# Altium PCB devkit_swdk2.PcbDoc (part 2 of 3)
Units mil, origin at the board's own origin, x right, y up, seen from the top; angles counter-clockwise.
Board outline 2700 x 2100 mil, 4 copper layers (Component Side, Internal Plane 1, Internal Layer 2, Bottom Layer), stack 57.8 mil thick; 223 components, 143 nets, 656 pads, 485 vias.
Unrouted connection lines stored in the file: 72.
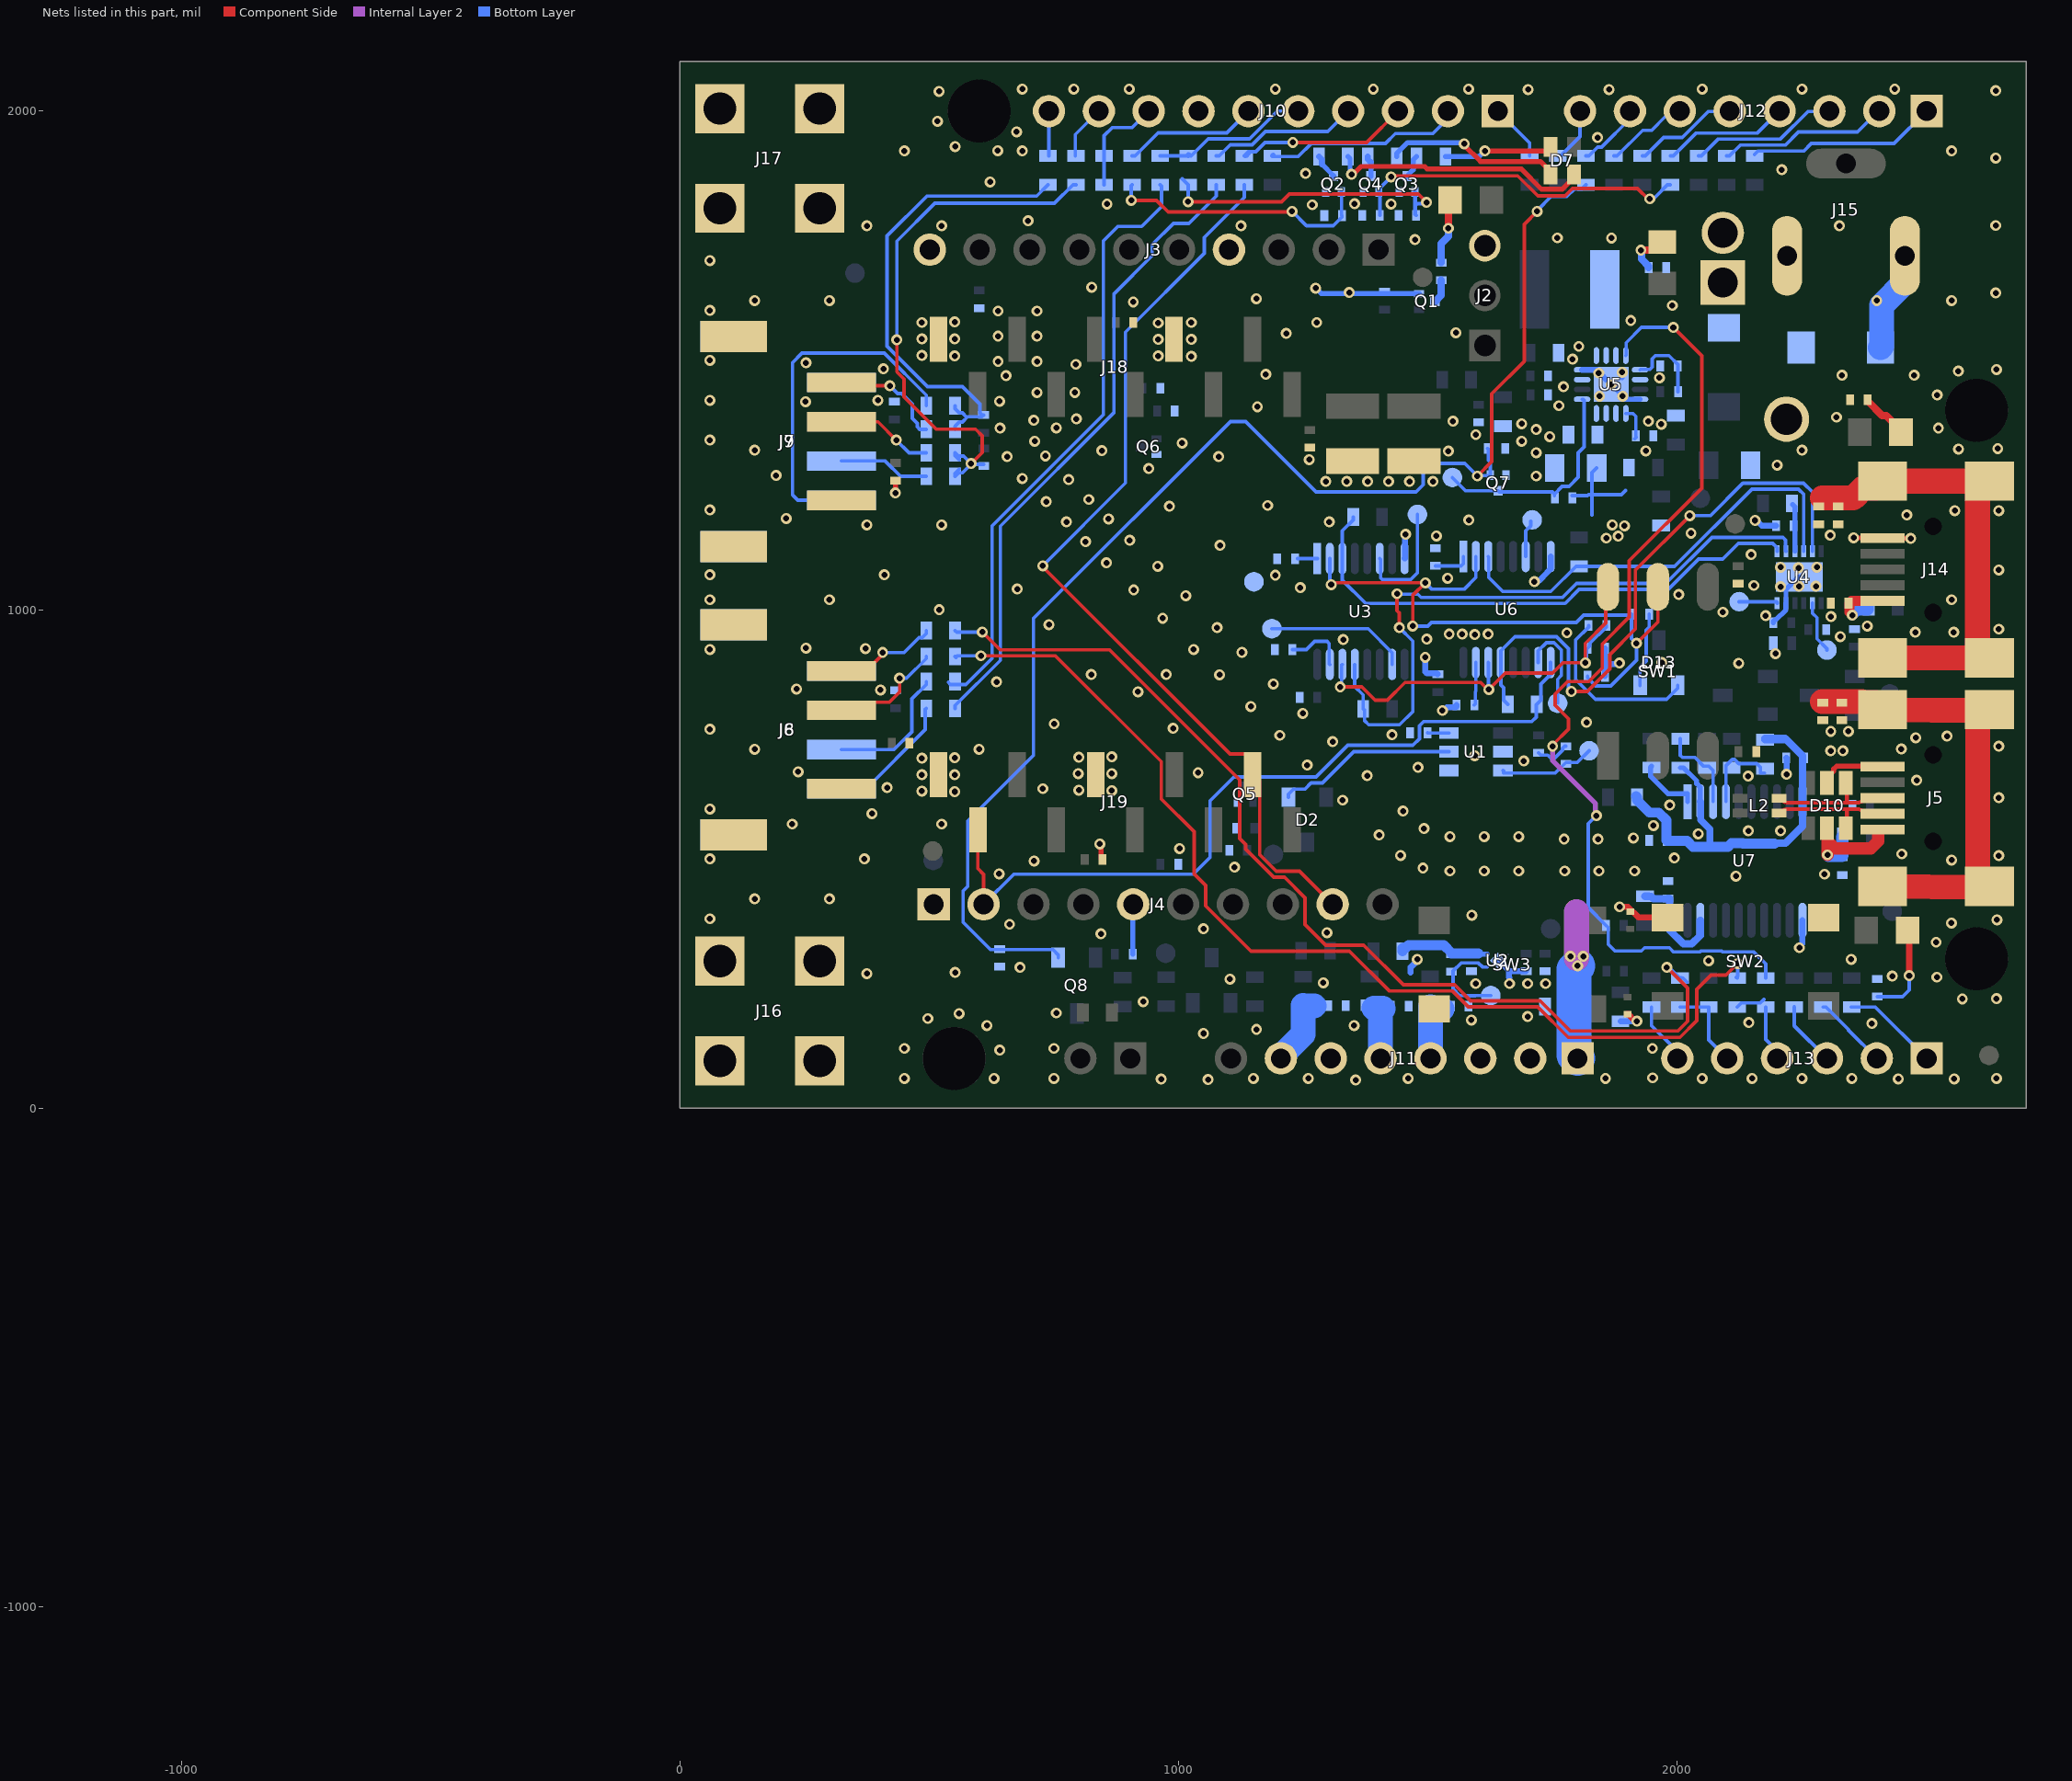
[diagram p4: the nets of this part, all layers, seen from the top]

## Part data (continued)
R8 R9 R10 R14 R15 R16 R17 R24 R25 R35: library part 1000796, "Resistor, 100K, 1%, 1/16W, 0402", Manufacturer1="Bourns Inc", Manufacturer2="Samsung Electro-Mechanics America, Inc", Manufacturer_Part_Number1=CR0402-FX-1003GLF, Manufacturer_Part_Number2=RC1005F104CS, Operating_Temperature="-55°C ~ 155°C", Power="0.063W, 1/16W", Resistance_Ohms=100k, Resistor_Package="0402 (1005 Metric)", Temperature_Coefficient=±100ppm/°C, Tolerance=±1%
R11 R12 R19 R20 R21 R22 R26 R32 R56: library part 1000795, "Resistor, 10K, 1%, 1/16W, 0402", Manufacturer1="Bourns Inc", Manufacturer_Part_Number1=CR0402-FX-1002GLF, Manufacturer_Part_Number2=CR0402-FX-1002GAS, Operating_Temperature="-55°C ~ 155°C", Power="0.063W, 1/16W", Resistance_Ohms=10k, Resistor_Package="0402 (1005 Metric)", Temperature_Coefficient=±100ppm/°C, Tolerance=±1%
R18 R23: library part 1000797, "Resistor, 1M, 1%, 1/16W, 0402", Manufacturer1="Bourns Inc", Manufacturer2="Samsung Electro-Mechanics America, Inc", Manufacturer_Part_Number1=CR0402-FX-1004GLF, Manufacturer_Part_Number2=RC1005F105CS, Operating_Temperature="-55°C ~ 155°C", Power="0.063W, 1/16W", Resistance_Ohms=1M, Resistor_Package="0402 (1005 Metric)", Temperature_Coefficient=±100ppm/°C, Tolerance=±1%
R30 R31: library part 1001865, "Resistor, 0, 1/16W, 0402", Manufacturer1="Bourns Inc", Manufacturer2="Samsung Electro-Mechanics America, Inc", Manufacturer_Part_Number1=CR0402-J/-000GLF, Manufacturer_Part_Number2=RCS1005J000CS, Operating_Temperature="-55C ~ 155C", Power=1/16W, Resistance_Ohms=0, Resistor_Package="0402 (1005 Metric)"
R33: library part 1001436, Manufacturer1="Panasonic Electronic Components", Manufacturer_Part_Number1=ERJ-2RKF7153X, Power=1/10W, Resistance_Ohms=715K, Resistor_Package="0402 (1005 Metric)", Tolerance=1%
R36: library part 1001435, Manufacturer1="Panasonic Electronic Components", Manufacturer_Part_Number1=ERJ-2RKF1783X, Power=1/10W, Resistance_Ohms=178K, Resistor_Package="0402 (1005 Metric)", Tolerance=1%
R54 R55: library part 1000583, "Resistor, 2.2K, 1%, 1/10W, 0402", Manufacturer1="Panasonic Electronic Components", Manufacturer_Part_Number1=ERJ-2RKF2201X, Operating_Temperature="-55°C ~ 155°C", Power="0.1W, 1/10W", Resistance_Ohms=2.2k, Resistor_Package="0402 (1005 Metric)", Temperature_Coefficient=±100ppm/°C, Tolerance=±1%
SB1 SB2 SB3 SB4 SB5 SB6 SB7 SB8 SB9 SB10 SB11 SB12 SB13 SB14 SB15 SB16 SB17 SB18 SB19 SB20 SB21 SB22 SB23 SB24 SB25 SB26 SB27 SB28 SB29 SB30 SB34 SB35 SB36 SB37 SB38 SB39 SB40 SB41 SB42 SB43 SB44 SB45 SB46 SB47 SB53: library part 1002269, "Resistor, Solder Bridge, 0, 1/10W, 0603", Manufacturer1="Panasonic Electronic Components", Manufacturer2=Yageo, Manufacturer_Part_Number1=ERJ-3GEY0R00V, Manufacturer_Part_Number2=RC0603JR-070RL, Operating_Temperature="-55°C ~ 155°C", Power=1/10W, Resistance_Ohms=0, Resistor_Package="0603 (1608 Metric)"
SB31 SB32 SB33 SB48 SB49 SB50 SB51 SB52: library part "Solder Bridge, Open"
SW1: library part 1002262, "Switch, SPST, DIP 3, 20V, 0.1A, Washable, Raised Actuator, SMD", Contact_Current_Rating_at_Voltage=0.1A, Manufacturer1=CTS, Manufacturer_Part_Number1=219-3MSTR, Operating_Temperature="-55°C ~ 85°C"
SW2 SW3: library part 1001120, "Switch, SPST-NO, 12V, 0.05A, 6.00x6.00mm, SMD", Contact_Current_Rating_at_Voltage="0.05A @ 12VDC", Current_Rating=-, Manufacturer1="C&K Components", Operating_Force=160gf, Operating_Temperature="-20°C ~ 60°C"
TP1 TP2 TP3 TP5 TP7 TP8 TP9 TP11 TP12 TP13 TP14 TP16 TP17 TP18 TP19 TP20: library part TP_1mm, "TEST POINT, SMD 1mm"
TP15: library part 1002259, "Connector, PC Test Point, 1 pin, Black, Silver Plate, TH, 3.17mmx11.30mm", Color=Black, Manufacturer1="Keystone Electronics", Manufacturer_Part_Number1=5011
U1: library part 1002129, "IC, Timer, 0.1-7200s, 1%, 1.8V-5.5V, TSOT-23-6", Manufacturer1="Texas Instruments", Manufacturer_Part_Number1=TPL5111DDCR, Operating_Temperature="-40C to +105C", Package_Case=TSOT-23-6, Voltage_Supply_Max=5.5V, Voltage_Supply_Min=1.8V, Voltage_Supply_Typical=3.3V
U2: library part 1001908, "IC, LDO, 1.8V, 300mA, 4-UDFN, 1.0x1.0mm", Current_Supply=300mA, Manufacturer1="ON Semiconductor", Operating_Temperature="-40C to 85C", Package_Case=4-UDFN, Voltage_Supply_Max="5.5 V", Voltage_Supply_Min=1.7V
U3 U6: library part 1001013, "IC, Multiplexer, Dual, 4:1, 4.5V-5.5V, SSOP-16", Manufacturer1="Texas Instruments", Package_Case=SSOP-16, Voltage_Supply_Typical=-
U4: library part 1001128, "IC, Interface, UART-USB, 5V, DFN, 3x3mm", Current_Supply=8mA, Manufacturer1="FTDI, Future Technology Devices International Ltd", Manufacturer_Part_Number1=FT234XD-R, Operating_Temperature="-40°C ~ 85°C", Package_Case="12-VFDFN Exposed Pad", Voltage_Supply_Max=5.5V, Voltage_Supply_Min=2.97V, Voltage_Supply_Typical=-
U5: "IC, Buck, ADJ, 3V-17V , 2A, QFN", Manufacturer1="Texas Instruments", Manufacturer_Part_Number1=TPS62140RGTR, Operating_Temperature="-40°C ~ 85°C", Package_Case="16-VFQFN Exposed Pad", Voltage_Supply_Typical=-
U7: library part 1001048, "IC, Level Shifter, Bidirectional, OD/Push/Pull , TSSOP-20", Manufacturer1="Texas Instruments", Operating_Temperature="-40°C ~ 85°C", Package_Case="20-TSSOP (0.173\", 4.40mm Width)", Voltage_Supply_Typical=-

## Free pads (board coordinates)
  round 125.98 hole 125.98: 0(550,100) 0(600,2000) 0(2600,300) 0(2600,1400)
  round 200 on Mech1: 0(550,100) 0(600,2000) 0(2600,300) 0(2600,1400)
  rect 39.37x39.37 on Mech13: 0(1800,100) 1(1640,2000) 1(2000,100) 1(2500,2000) 2(1640,2000) 2(2000,100) 2(2500,2000)
  oval 20x50 on Mech15: 3(1069.83,1431.81) 4(361.34,668.98) 5(280,295) 6(280,2005) 7(2600,1400) 8(600,2000) 9(550,100) 11(2220,1709.69)
  oval 50x20 on Mech15: 10(2529.69,313.39) 12(1800,100) 13(2000,100) 14(2500,2000) 15(1640,2000) 16(190.32,1122.61)

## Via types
v1: diameter 22, hole 12, Component Side to Bottom Layer, 485 vias

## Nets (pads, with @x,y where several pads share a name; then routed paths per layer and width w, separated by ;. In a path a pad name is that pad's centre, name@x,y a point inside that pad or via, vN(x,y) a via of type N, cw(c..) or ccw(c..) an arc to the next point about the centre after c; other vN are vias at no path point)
ARD_A0: J13.6 SB24.2 | length 124.4
  Bottom Layer w7: SB24.2@1948.25,203 1948.25,165.75 2000,114 J13.6@2000,100
ARD_A1: J13.5 SB25.2 SB53.2 | length 175.7
  Bottom Layer w7: SB25.2@2005.5,203 2062.75,203 2062.75,137.25 J13.5@2100,100
ARD_A2: J13.4 SB26.2 SB30.2 | length 172.3
  Bottom Layer w7: SB26.2@2120,203 2128.31,211.31 2166.31,211.31 2173.5,218.5 ; SB30.2@2177.37,203 2177.37,138.19 2200,115.56 J13.4@2200,100
ARD_A3: J13.3 SB27.2 | length 130
  Bottom Layer w7.55: SB27.2@2234.75,203 2234.75,165.25 J13.3@2300,100
ARD_A4: J13.2 SB28.2 | length 151.1
  Bottom Layer w7: SB28.2@2292.25,203 2298.16,203 2343.33,157.83 2343.33,156.67 J13.2@2400,100
ARD_A5: J13.1 SB29.2 | length 193.7
  Bottom Layer w7: SB29.2@2349,203 2397,203 J13.1@2500,100
ARD_AREF: J10.8 SB8.1 SB8.2 | length 208.3
  Bottom Layer w7: SB8.2@850.5,1852.19 SB8.1@850.5,1910.19 850.5,1950.5 867,1967 907,1967 J10.8@940,2000
ARD_IO0: J12.1 SB23.1 | length 381.3
  Bottom Layer w7: SB23.1@2154.78,1913.01 2161.78,1920 2253.68,1920 2268.5,1934.82 2434.82,1934.82 J12.1@2500,2000
ARD_IO1: J12.2 SB22.1 | length 343.4
  Bottom Layer w7: SB22.1@2098.87,1910.01 2104.78,1910.01 2126.77,1932 2217,1932 2243,1958 2361.26,1958 2403.26,2000 J12.2@2405,2000
ARD_IO2: J12.3 SB21.1 | length 299.8
  Bottom Layer w7: SB21.1@2042.46,1910.01 2048.37,1910.01 2082.36,1944 2206.98,1944 2262,1999.02 2304.02,1999.02 J12.3@2305,2000
ARD_IO3: J12.4 SB20.1 | length 256.2
  Bottom Layer w7: SB20.1@1986.05,1910.01 1991.96,1910.01 2037.95,1956 2161,1956 J12.4@2205,2000
ARD_IO4: J12.5 SB19.1 | length 212.6
  Bottom Layer w7: SB19.1@1929.64,1910.01 1935.55,1910.01 1972.54,1947 2009.98,1947 2062,1999.02 2104.02,1999.02 J12.5@2105,2000
ARD_IO5: J12.6 SB18.1 | length 169
  Bottom Layer w7: SB18.1@1873.23,1910.01 1879.14,1910.01 1930.63,1961.5 1948.5,1961.5 1975.9,1988.9 1993.9,1988.9 J12.6@2005,2000
ARD_IO6: J12.7 SB17.1 | length 134.6
  Bottom Layer w7: SB17.1@1816.82,1910.01 1822.73,1910.01 1840.22,1927.5 1848.08,1927.5 1905,1984.42 J12.7@1905,2000
ARD_IO7: J12.8 SB16.1 | length 111.9
  Bottom Layer w7: SB16.1@1760.41,1910.01 1766.32,1910.01 1805,1948.69 J12.8@1805,2000
ARD_IO8: J10.1 SB15.1 | length 119.4
  Bottom Layer w7: J10.1@1637.99,1997.99 J10.1@1640,2000 1704,1936 SB15.1@1704,1910.01
ARD_IO9: J10.2 SB14.1 | length 401.2
  Bottom Layer w7: SB14.1@1188,1910.19 1189.25,1908.94 1239.84,1908.94 1266.06,1935.15 1414.9,1935.15 1434.75,1955 1509.5,1955 1540,1985.5 J10.2@1540,2000
  Bottom Layer w10: SB14.1@1188,1910.19 SB14.1@1189.75,1911.94
ARD_IO10: J10.3 SB13.1 | length 359
  Component Side w7: v1@1229.5,1937 1377,1937 J10.3@1440,2000
  Bottom Layer w7: SB13.1@1131.75,1910.19 1140.06,1918.5 1154.76,1918.5 1173.26,1937 v1@1230,1937 ; SB13.1@1134.19,1910.19 SB13.1@1137.66,1910.19
  Bottom Layer w10: SB13.1@1134.19,1910.19 SB13.1@1141,1917
  other v1: 1229,1937
ARD_IO11: J10.4 SB12.1 | length 301.7
  Bottom Layer w7: SB12.1@1075.5,1910.19 1081.41,1910.19 1103.72,1932.5 1147.45,1932.5 1173.95,1959 1299,1959 J10.4@1340,2000
ARD_IO12: J10.5 SB9.1 SB11.1 | length 318.1
  Bottom Layer w7: SB9.1@963,1910.19 SB11.1@1019.25,1910.19 1025.16,1910.19 1059.47,1944.5 1142.48,1944.5 1197.98,2000 J10.5@1240,2000
  Bottom Layer w10: SB11.1@1019.25,1910.19 1021,1911.94 SB11.1@1020,1912.94
ARD_IO13: J10.6 SB10.1 | length 270.5
  Bottom Layer w7: SB10.1@906.75,1910.19 912.66,1910.19 958.97,1956.5 1096.5,1956.5 J10.6@1140,2000
ARD_RESET: J11.6
ARD_SCL: J10.10 SB6.1 | length 89.8
  Bottom Layer w7: SB6.1@740,1910.19 J10.10@740,2000
ARD_SDA: J10.9 SB7.1 | length 109.3
  Bottom Layer w7: SB7.1@793,1910.19 793,1953 J10.9@840,2000
CON_USB_N: D10.6 J5.2 L2.3 | length 264.3
  Component Side w7.55: L2.3@2204.37,592.43 cw(c2222.98,573.82) 2222.98,600.14 2340,600.14 ; D10.6@2337.4,562 2340,564.6 2340,600.14 ; J5.2@2411.43,590.67 J5.2@2383.68,590.67 ; 2340,600.14 2360.81,600.14 cw(c2360.81,583.97) J5.2@2372.24,595.42 ; J5.2@2372.25,595.41 ccw(c2383.68,606.84) J5.2@2372.29,595.36 ; J5.2@2372.25,595.41 J5.2@2372.29,595.36 ; J5.2@2372.29,595.36 ccw(c2383.68,606.84) J5.2@2383.63,590.67 ; J5.2@2372.29,595.36 2376.99,590.67 J5.2@2383.63,590.67 ; J5.2@2383.63,590.67 ccw(c2383.68,606.84) J5.2@2383.68,590.67 ; J5.2@2383.63,590.67 J5.2@2383.68,590.67
CON_USB_P: D10.1 J5.3 L2.4 | length 266.6
  Component Side w7.55: L2.4@2204.37,621.57 2206.34,619.59 ccw(c2223,636.25) 2223,612.69 2340,612.69 ; D10.1@2337.4,652.55 2340,649.95 2340,612.69 ; J5.3@2372.24,617.42 cw(c2360.81,628.86) 2360.81,612.69 2340,612.69 ; J5.3@2411.43,622.17 J5.3@2383.68,622.17 ; J5.3@2383.68,622.17 ccw(c2383.68,605.99) 2372.26,617.44 2376.99,622.17 J5.3@2383.68,622.17
FTDI_CTS#: SB51.2 U4.11 U6.13 | length 1222.7
  Component Side w7: v1(1787.5,836) 1819.52,836 1864.5,880.98 1864.5,909.74 1916,961.24 1916,1079.5 v1(2025,1188.5)
  Bottom Layer w7: SB51.2@1660,810 1651.69,818.31 1651.69,843.23 1646,848.92 U6.13@1646,893.92 1646,917.54 1674.37,945.92 1757.75,945.92 1782,921.67 v1@1782,839.1 ; v1(2025,1188.5) 2066.08,1188.5 2131.52,1253.94 2253,1253.94 2271,1235.94 U4.11@2271,1117.17
FTDI_RTS#: SB50.2 U3.13 U4.8 | length 1338.7
  Component Side w7: v1(1438,1032) 1438,997.94 1442.5,993.44 v1(1442.5,964)
  Bottom Layer w7: U3.13@1353.25,890.08 1353.25,846.03 1370.15,829.13 SB50.2@1370.15,801 1373,798.15 1373,777 1381,769 1442.95,769 1469.63,795.67 1469.63,936.87 v1(1442.5,964) ; v1(1438,1032) 1439,1031 1479.9,1031 1486.4,1024.5 1770.05,1024.5 1798.02,1052.48 1976.87,1052.48 2069.24,1144.84 2211.85,1144.84 2217.22,1139.48 2217.22,1117.8 U4.8@2217.85,1117.17
FTDI_RXD: SB49.2 U4.10 U6.3 | length 889.3
  Bottom Layer w7: U6.3@1621,1106.52 1621.82,1105.7 1621.82,1064.52 1649.84,1036.5 1746.41,1036.5 1796.91,1087 SB49.2@1802.82,1087 1994.43,1087 2149.36,1241.94 2243,1241.94 2253.28,1231.66 U4.10@2253.28,1117.17
FTDI_TXD: SB48.2 U3.3 U4.7 | length 1087.4
  Bottom Layer w7: SB48.2@1350,1186 1350,1180.09 1328.25,1158.35 U3.3@1328.25,1102.68 1328.25,1059.25 1375,1012.5 1446.08,1012.5 1481.43,1012.5 1775.02,1012.5 1802.99,1040.48 1981.84,1040.48 2042.86,1101.5 2091,1101.5 2122.34,1132.84 2191.34,1132.84 2200.13,1124.06 U4.7@2200.13,1117.17
GND: C1.2 C2.2 C3.2 C4.2 C5.2 C6.2 C7.2 C8.2 C9.2 C10.2 C11.2 C12.2 C13.2 C14.2 C15.1 C16.2 C17.2 C18.2 C19.2 C20.2 C21.2 C22.2 C23.2 C24.2 C25.2 C26.2 C27.1 C28.2 C29.2 C30.2 C31.2 C32.2 C33.2 C34.2 C35.2 C36.2 C37.2 C38.2 C39.2 C40.2 C41.2 C42.2 C43.2 C44.2 C45.2 C46.2 C47.2 D8.A D10.2 D14.A D15.A J2.3 J3.4 J3.10 J4.1 J4.5 J5.5 J6.1 J6.5 J7.1 J7.5 J8.1 J8.5 J9.1 J9.5 J10.7 J11.2 J11.3 J14.5 J15.3 J16.1 J17.1 J18.4 J18.10 J19.1 J19.5 J20.2 Q1.2 Q2.2 Q3.2 Q4.2 Q5.2 Q6.2 Q7.2 R1.1 R2.1 R6.1 R7.1 R8.1 R9.1 R10.1 R11.2 R12.2 R14.1 R16.1 R18.1 R19.1 R20.1 R21.1 R22.1 R23.1 R24.1 R25.1 R26.1 R36.1 R37.1 R56.1 R59.1 R60.1 SW2.3 SW2.4 SW3.3 TP9.1 TP15.1 U1.2 U1.4 U2.2 U2.5 U3.8 U4.5 U4.13 U5.6 U5.8 U5.15 U5.16 U5.17 U6.8 U7.11 | length 1845.6
  Component Side w10: v1(432.15,1234) C20.2@432.15,1258.82 ; v1(842,530) 842,526.75 844.3,524.45 844.3,502.03 C24.2@847.18,499.15 ; D10.2@2300,652.55 2300,662.39 2313.62,676.01 2313.62,680.31 2319.48,686.17 2410.42,686.17 J5.5@2411.43,685.16 ; v1(2353.66,1144) 2409.03,1144 2410.03,1143 v1(2468,1143)
  Component Side w12: v1(1884.5,404) 1884.57,403.93 1901.29,403.93 1922.64,382.58 SW2.4@1980.5,382.58 ; D14.A@1899.6,188.38 D14.A@1900,188.78 1901.48,188.78 1913.84,176.41 1917.09,176.41 v1(1919,174.5)
  Bottom Layer w7: C4.2@1721.85,712.82 1726.22,708.45 1739.97,708.45 1748.92,699.5 1751.08,699.5 1769.52,717.94 1769.52,721.66 1773.89,726.04 R26.1@1776.85,726.04
  Bottom Layer w10: C45.2@908,309 908.5,309.5 908.5,389.5 J4.5@909,390 ; v1(1275,1645) 1286.25,1633.75 Q1.2@1482.25,1633.75 ; v1@1454.13,1150.13 v1(1455,1151) ; v1(1867.19,1451.53) 1896.72,1422 U5.8@1925.26,1422 ; U5.17@1889.26,1465.37 U5.17@1889.46,1465.57 ; C5.2@2192.83,973.99 2192.83,976.95 2195.7,979.82 2198,979.82 2217.77,999.6 U4.5@2217.85,1012.83 U4.5@2217.85,1012.83 2217.85,1040.97 2242.38,1065.5 U4.13@2244.43,1065.5 ; v1@2216.7,672.3 v1(2219,670)
  Bottom Layer w12: U3.8@1453.25,1102.68 1453.97,1103.4 1453.97,1149.97 v1@1454.13,1150.13 ; 1465.5,272 1465.5,282.79 1478.5,295.79 v1(1478.5,298.5) ; v1(1494.5,904.5) 1494.5,875.5 1497.89,872.11 1517.97,872.11 C42.2@1519.85,870.24 ; v1(1497.5,941) v1@1497.5,943 ; v1(1529,797.74) 1531.71,797.74 1537.99,804.02 1555.67,804.02 1557.54,805.89 R20.1@1557.54,808.85 ; U2.5@1640,296 1643,296 1662,277 ; 1663,262 1662,263 1662,277 ; C37.2@1696.85,274.82 1664.18,274.82 1662,277 ; v1(1713.27,1056) 1715.18,1057.91 1722.71,1057.91 1739.87,1075.08 1739.87,1075.76 1746,1081.88 U6.8@1746,1106.52 ; U5.16@1809.12,1481.06 1809.61,1480.57 1838.15,1480.57 v1(1867.19,1451.53) ; R24.1@1855.43,866.62 1855.43,889.5 ; R25.1@1855.43,922.51 1855.43,889.5 ; v1(1884,893) 1882.09,891.09 1857.02,891.09 1855.43,889.5 ; C39.2@1886,174.5 v1(1919,174.5) ; v1(2156,1179) 2158.71,1179 2169.26,1168.44 C21.2@2198.04,1168.44 ; v1@2216.7,672.3 2218.87,674.46 2218.87,702.72 R14.1@2218.74,702.85 ; v1(2245,322) 2245,324.71 2250.23,329.94 2250.23,376.23 U7.11@2251,377
  Bottom Layer w50: D8.A@2407.33,1526 2409.89,1528.56 2409.89,1610.65 2456.22,1656.98 J15.3@2456.22,1709.69
  other v1: 1355,56.5 965,58.5 1059,57.5 2443,59 2555,59 450,60 630,60 750,60 1150,60 1260,60 1460,60 1856,60 2050,60 2150,60 2250,60 2350,60 2640,60 1950.5,61 641.5,116.5 450,120 750,120 1950,120 1050,150 1156.16,158 615.5,166 1352,166 2390,170 2143.5,172 1586.97,177 497,180 1700,184 560,190 754.87,191 929,214 2571.5,219.5 2640,220 1595.69,250 1663.5,250 1699.75,250 1736,250 1290,251.5 1103,259 2520.5,263 2431,265 375,270 552.03,272.32 682,282.74 2062.82,296 2348.5,298.5 2519,333 844.19,349.81 1297.5,352 1050,360 661,369 2549.5,371.5 2641,378 60,380 1588,387 150,420 300,420 2117.5,465.5 640,470 2295,469.5 1544,476 1613,476 1682,476 1774,476 1843,476 1914.19,476 1490,481.83 1112,483.5 710.29,496 2550,498 60,500 370,500 1994,502 2644.5,506.5 1445,507 2450,510 1002,521 1773,540 1841,540 1912,542 1544,545 1613,545 1682,545 1402,548.26 2042,550.5 2142.5,556.5 2207,556.5 1492,561 1952,567 225,570 525,570 385,591 1450,596 60,600 1985,608 1329,618 2644.5,623 551,635 485,636 866,637 800,638 727.52,641 415.5,643 2480,658 2142,666 1378,667 485,669 551,669 798.5,671 866,671 1039,673 237,675 1480,683.49 1258,688.21 1692.05,696.74 485,702 551,703 800,704 866,705 1594,707 2307.5,717 2332,717 150,720 600,720 2449,720.5 2644.5,726 1309,735.19 2478,743 2541,746.5 1203,748 1428,749 2307.82,756 2343,756 60,760 988.97,762 750.5,771 1818,774 1249,792 1145,805.94 918.58,835.15 402,839 234,840.85 1190,851 635,855 1082,869.23 825,870 975,870 2123,892.5 1969,894 2197,912 1127,914.38 60,920 1030,920 372,922 253,923 1330,940 2327,946 1778.5,953.5 2477.15,954.74 2554.15,954.74 2644.5,961 1077,964.14 2381,967 740,970 968,983 2308,986 2177,988 2091.5,995 520,1000 60,1020 300,1020 2550,1020 1014.24,1028 2003,1030.5 910,1039.5 676.5,1041.5 1244.19,1044 2207,1046 2244,1047 2278,1047 2153.5,1048.5 1539.58,1063 1194,1069 60,1070 410,1070 2644.5,1079.75 2243,1084 2207,1085 2280,1085 958,1087 855.28,1094 2148,1110.5 1083,1129 813.5,1136.5 902,1139 1516.87,1148 2306.8,1149.37 2027.5,1153.5 375,1170 525,1170 775,1176 1301.92,1176.03 1582,1179.59 859.59,1182 213,1183 2460,1190 2556.5,1198.5 2644.5,1198.5 60,1200 981.5,1207.5 1178.5,1209 734.5,1216.5 820,1221 1295,1257 1337,1257 1379,1257 1421,1257 1463,1257 1510,1257 779.5,1261 686.73,1263 1717,1268 193,1269 940,1283 2200,1290 1262,1301 656,1307 1080.15,1307 733,1308.14 1717,1314.59 1541,1318 1937,1318.5 846,1319 150,1320 2250,1320 2564,1322 2642.5,1323 1007,1334 711.64,1337.89 1688,1337.89 60,1340 1743.98,1347 1596,1351 1717,1361.19 642,1364 2523.5,1364 754.87,1364.71 1968,1372 1688,1373 1550,1378 1942,1378 709.69,1379.86 795,1382.76 2319,1386 1158,1407 1762.5,1409 252,1417 641,1418 60,1420 397,1420 1844,1428 1890.5,1428 2521,1430.5 716,1435.5 792,1435.5 1772,1447 1964,1465 654,1469.44 2330,1470 2475,1470 1175,1472 1842.5,1474.5 1889.26,1476 2563.5,1478.5 2640,1481.5 408,1483 794,1492 253,1495 638,1498 716,1498 60,1500 1790,1502.5 1025.5,1508 551,1509 959,1509 485,1510 1802.5,1528 959,1542 1025.5,1542 485,1543 551,1543 638,1548.5 716,1548.5 1216,1554 1556,1555.5 959,1575 485,1576 1025.5,1576 1277,1576 551,1577 1906.65,1579.76 638,1599 716,1599 60,1600 1990,1610 909,1617 150,1620 300,1620 2400,1620 2550,1620 1156,1623.5 2638.5,1635.25 1342,1636 826,1646.5 60,1700 1474,1742 1759.35,1745.6 1868,1745.5 375,1770 525,1770 1125,1770 2325,1770 2638.5,1770.5 698,1780 1268,1812 856.5,1813.5 1353,1814 1426,1813.5 622,1857.67 1254.47,1875.12 2209.5,1882.5 2638.5,1905.75 450,1920 637.5,1920.5 686.73,1920 2550,1920 552,1929 1840,1947 675,1958.5 516.5,1979.5 519.5,2039.5 2638.5,2041 1701,2043 1863,2043 686.73,2044 790,2044 901,2044 1194,2044 1390.36,2044 1581.41,2044 2050,2044 2250,2044 2436,2044
Grove_IO1: SB25.1 SB34.2 | length 2091
  Component Side w7: v1(606.5,955) 642,919.5 861.81,919.5 1122.72,658.59 1122.72,540.86 1134.5,529.08 1134.5,519.95 1190.95,463.5 1212.48,463.5 1253.7,422.28 1253.7,368.22 1294.92,327 1371.03,327 1450.55,247.48 1553.66,247.48 1585.64,215.5 1724.97,215.5 1785.47,155 2001.16,155 2020.5,174.34 2020.5,241 v1(1979,282.5)
  Bottom Layer w7: SB34.2@552.03,958 555.03,955 v1(606.5,955) ; v1(1979,282.5) 1982.63,282.5 2003.7,261.43 SB25.1@2009.1,261.43 ; SB25.1@2011.41,261 SB25.1@2019.72,252.69
Grove_IO2: SB26.1 SB35.2 | length 2134.6
  Component Side w7: v1(603.5,907.5) 753,907.5 965.24,695.26 965.24,620.38 1031,554.62 1031,470.03 1054.01,447.02 1054.01,406.01 1145.02,315 1342.5,315 1422.02,235.48 1548.69,235.48 1580.67,203.5 1720,203.5 1781.31,142.19 2005.32,142.19 2039,175.87 2039,238.5 2067.5,267 2097.5,267 v1(2121,290.5)
  Bottom Layer w7: SB35.2@552.03,906 553.53,904.5 556.53,907.5 v1(603.5,907.5) ; SB26.1@2120,261 2118.5,262.5 2121,265 v1(2121,290.5)
Grove_IO3: SB12.2 SB37.2 | length 1285.2
  Bottom Layer w7: SB37.2@552.03,802 552.03,807.91 642.5,898.37 642.5,1167.5 870.5,1395.5 870.5,1633.52 947,1710.02 947,1732 989.5,1774.5 1020.5,1774.5 1075.5,1829.5 SB12.2@1075.5,1852.19
Grove_IO4: SB9.2 SB36.2 | length 1230.6
  Bottom Layer w7: 538.5,854.5 538.5,854.1 542.6,850 573.58,850 626,902.42 626,1168 849,1391 849,1739.5 878.25,1768.75 925.83,1768.75 965.5,1808.42 965.5,1849.69 SB9.2@963,1852.19
Grove_SCL: R55.1 SB6.2 SB39.2 SB41.2 | length 956.8
  Bottom Layer w7: SB39.2@552.03,1361.83 552.03,1367.74 560.34,1376.05 566.25,1376.05 577.02,1386.82 ; SB41.2@552.03,1408.94 552.03,1403.04 560.34,1394.73 566.25,1394.73 574.15,1386.82 577.02,1386.82 ; SB6.2@738,1852.19 715.31,1829.5 495.5,1829.5 415.5,1749.5 415.5,1528.5 496.5,1447.5 566.5,1447.5 601.55,1412.45 601.55,1394.58 605.93,1390.2 R55.1@608.88,1390.2 605.5,1386.82 577.02,1386.82
Grove_SDA: R54.1 SB7.2 SB38.2 SB40.2 | length 1123.2
  Component Side w7: v1(435,1541) 435,1477.11 449.5,1462.61 449.5,1426.5 514,1362 592.7,1362 606,1348.7 606,1315 v1(584,1293)
  Bottom Layer w7: v1(435,1541) 435,1739 511,1815 751.15,1815 788.34,1852.19 SB7.2@794.25,1852.19 ; SB40.2@560.34,1281.83 552.03,1273.52 SB40.2@552.03,1267.61 558.92,1274.5 566.5,1274.5 584,1292 v1(584,1293) 568.8,1308.2 558.55,1308.2 SB38.2@552.03,1314.72 552.03,1308.82 SB38.2@560.34,1300.5 ; v1@584,1291.69 609.19,1291.69 R54.1@609.5,1292
LED_BLUE: Q3.1 R8.2 SB11.2 | length 664.5
  Component Side w7: v1(1019,1818) 1206.5,1818 1222,1833.5 1480.63,1833.5 v1(1497.13,1817)
  Bottom Layer w7: SB11.2@1007.47,1863.97 SB11.2@1017.5,1853.94 ; v1(1019,1818) 1019,1852.44 SB11.2@1017.5,1853.94 ; SB11.2@1019.25,1852.19 SB11.2@1017.5,1853.94 ; R8.2@1476.43,1790.59 R8.2@1475.22,1791.81 ; v1(1497.13,1817) 1494.26,1814.13 1479.35,1814.13 1475.22,1810 ; R8.2@1475.22,1791.81 1475.22,1810 ; R8.2@1475.22,1791.81 1474,1793.02 Q3.1@1474,1838 1475.22,1836.79 1475.22,1810
LED_GREEN: Q2.1 R9.2 SB10.2 | length 535.2
  Component Side w7: v1(905,1821) 955.5,1821 979,1797.5 1226,1797.5 v1(1227.5,1799)
  Bottom Layer w7: v1(905,1821) 905,1850.44 SB10.2@906.75,1852.19 ; v1(1227.5,1799) 1256.5,1770 1310.08,1770 1327.57,1787.49 R9.2@1327.57,1790.44 1326.85,1791.15 1326.85,1837.29 Q2.1@1326.14,1838
LED_ORANGE: Q4.1 R10.2 SB20.2 | length 693.5
  Component Side w7: v1(1426,1868) 1428.06,1870.06 1679.94,1870.06 1720.3,1829.7 1774.81,1829.7 1789.62,1844.5 1920.33,1844.5 v1@1942.83,1822
  Bottom Layer w7: Q4.1@1401.5,1836.96 1402.53,1836.96 Q4.1@1401.5,1838 ; R10.2@1403.57,1790.59 1403.57,1845.57 v1(1426,1868) ; v1@1944.83,1820 1951.7,1826.87 1955.01,1826.87 1980.15,1852.01 SB20.2@1986.05,1852.01
  other v1: 1944.83,1824
MUX_S0: R25.2 R30.1 SW1.6 U3.14 U6.14 | length 909.6
  Component Side w7: v1(1324,845) 1367.42,845 1393.92,818.5 1418.5,818.5 1453.93,853.93 1605.52,853.93 1619.45,840 v1(1622,840) 1655,873 1750.05,873 1770.55,893.5 v1(1815.5,893.5) 1815.5,932.47 1856.61,973.58 1856.61,1041.45 SW1.6@1861,1045.83
  Bottom Layer w7: v1(1324,845) 1326.58,847.58 1326.58,888.41 U3.14@1328.25,890.08 ; U6.14@1621,893.92 1621.5,893.42 1621.5,840.5 v1(1622,840) ; v1(1815.5,893.5) 1817.75,895.75 1817.75,920.26 R25.2@1820,922.51 1824.37,926.88 1824.37,932.23 1857.5,965.35 R30.1@1857.5,968.31
MUX_S1: R24.2 R31.1 SW1.5 U3.2 U6.2 | length 1299.7
  Component Side w7: v1@1310,1054 v1(1495,1054) 1469.5,1028.5 v1(1469.5,967) ; v1(1918,932.5) 1961,975.5 SW1.5@1961,1045.83
  Bottom Layer w7: U3.2@1303.25,1102.68 1303.25,1052.75 v1(1306,1050) ; v1(1469.5,967) 1499.5,967 1507,974.5 1797.54,974.5 1812.06,989.02 1906.42,989.02 R31.1@1908.24,990.85 1908.24,942.26 v1(1918,932.5) 1918,898.46 1866.83,847.29 1836.37,847.29 1820,863.66 R24.2@1820,866.62 ; v1(1495,1054) 1508,1041 1572.53,1041 1596,1064.47 U6.2@1596,1106.52
NetC8_1: C8.1 C35.1 FB1.2 R15.2 U5.10 U5.11 U5.12 | length 208.8
  Bottom Layer w7: R15.2@1789.18,1228.85 1820,1228.85 1821.84,1230.69 1829,1230.69 ; 1829,1190 1829,1230.69 ; C8.1@1838.18,1284 1829,1274.82 1829,1230.69 ; 1896,1239 1887.69,1230.69 1829,1230.69
NetC12_1: C12.1 U5.9 | length 66.1
  Bottom Layer w7: U5.9@1896.72,1393.46 1911,1393.46 1916.74,1387.71 C12.1@1916.74,1348.85 ; C12.1@1914.37,1342.69 C12.1@1917.77,1346.09
NetC13_1: C13.1 FB3.1 J14.1 | length 129.2
  Component Side w20: C13.1@2345.38,1012.02 2345.38,995.16 2351,989.54 v1(2351,989) ; C13.1@2349.18,1017.46 2409.27,1017.46 J14.1@2409.43,1017.62
  Bottom Layer w20: v1(2351,989) 2351.54,989 2360.82,998.28 2382.19,998.28 2384,1000.09 FB3.1@2384,1006
NetC15_2: C15.2 J14.6 R2.2 | length 821.4
  Component Side w50: 2290.95,1224 2352.76,1224 2372.17,1243.41 2397.06,1243.41 J14.6@2411.43,1257.78 2602,1257.78 2602,903.45 J14.6@2460,903.45
NetC21_1: C21.1 SB1.2 U4.9 | length 95.7
  Bottom Layer w10: SB1.2@2231,1211 2235.49,1206.51 2235.49,1165.81 2235.49,1117.24 U4.9@2235.57,1117.17
NetC26_1: C26.1 D10.5 FB2.2 J5.1 | length 227.9
  Component Side w15: J5.1@2403.34,559.17 J5.1@2411.43,559.17
  Component Side w25: v1@2301.28,508.43 2301.28,535.52 2315.92,520.88 2370.88,520.88 2371,521 2388,521 2403,536 2403,548.26
  Bottom Layer w25: v1@2303.18,506.1 2329.85,506.1 2331.14,507.39 2331.14,544.31 FB2.2@2331.82,545
  other v1: 2301.06,508.22
NetC27_2: C27.2 J5.6 R60.2 | length 863.9
  Component Side w50: C27.2@2290.95,816.05 2329.73,816.05 2369.71,816.05 2372.06,813.7 2397.06,813.7 J5.6@2411.43,799.33 2602.5,797.83 2602.5,443.5 J5.6@2411.43,445
NetC28_1: C28.1 J11.7 SB2.2 | length 146.9
  Bottom Layer w50: J11.7@1205,100 1205,104.06 1249.63,148.69 SB2.2@1249.63,206 1250.63,205 1271.63,205
NetC29_1: C29.1 J11.5 SB3.2 | length 114.3
  Bottom Layer w50: SB3.2@1392.24,200.87 1408.73,200.87 1410.03,199.57 ; J11.5@1405,100 1405,196
NetC30_1: C30.1 J11.4 SB4.2 | length 126.7
  Bottom Layer w50: J11.4@1505,100 SB4.2@1505,198.85 ; SB4.2@1505,203.74 SB4.2@1505,198.85 ; 1528,198.85 SB4.2@1505,198.85
NetC31_1: C31.1 J11.1 SB5.2 | length 285.4
  Internal Layer 2 w50: 1798,300 1798,394.02
  Bottom Layer w70: J11.1@1800,100 1793,107 1793,278.62 v1(1800,285.62)
  other v1: 1785.51,304.82 1811.33,304.82 1594,950 1542.5,951 1568.5,951 1620.5,951 1857.5,1143.5 1881.5,1147.5 1894,1168 1869.5,1170
NetC32_1: C32.1 R5.2 R13.2 R14.2 SB43.2 U7.2 U7.10 | length 881.8
  Bottom Layer w10: R5.2@2006.38,682.99 2012.28,682.99 2038.6,656.68 2038.6,651.22 2046.2,643.62 U7.2@2046.2,615
  Bottom Layer w14: U7.2@2046.2,615 2046.58,614.62 2046.58,578.44 2065,560.03 2065,529 2063,527
  Bottom Layer w15: R13.2@2176,739 2218.97,739 ; R13.2@2176,741.76 2216.21,741.76 2218.97,739 ; 2191.23,531.5 2216.73,531.5 2250.81,565.57 2250.81,614.81 U7.10@2251,615 2251,706.97 2218.97,739
  Bottom Layer w20: SB43.2@1917.19,625.81 SB43.2@1919,624 1919,618.09 1944.09,593 1962.77,593 1978,577.77 1978,537.79 C32.1@1978.63,537.15 1979.46,536.33 2019.4,536.33 2031.23,524.5 2101.73,524.5 2108.73,531.5 2130.73,531.5 2131.73,530.5 2194.73,530.5
NetC33_1: C33.1 SB44.1 U7.19 | length 222.3
  Bottom Layer w15: SB44.1@1935.3,425.13 1941.87,425.13 1942,425 1947.91,425 1952.62,420.29 1980.98,420.29 C33.1@1981.26,420.57 ; C33.1@1984.21,420.57 1984.58,420.19 1984.58,357.02 2012.11,329.5 2029.09,329.5 2046.01,346.42 2046.01,376.81 U7.19@2046.2,377
NetC36_1: C36.1 R17.2 SB42.2 U2.4 | length 183.5
  Bottom Layer w10: 1600.85,310.18 1602.23,308.8 U2.4@1618.94,308.8
  Bottom Layer w20: SB42.2@1449,315 1449,320.91 1450.81,322.72 1456.72,322.72 1461,327 1531.73,327 1547,311.73 R17.2@1547,310.43 ; R17.2@1550.08,310.25 1550.15,310.18 1587,310.18 1600.85,310.18
NetD1_2: D1.2 R58.2 | length 133.2
  Component Side w15: v1(1541,1765) 1541,1818.49 D1.2@1544.51,1822
  Bottom Layer w15: R58.2@1526.62,1696.18 1526.62,1734.26 1541,1748.64 v1(1541,1765)
NetD2_1: D2.1 U1.5 | length 362.9
  Bottom Layer w7: D2.1@1220.41,624 1220.41,629.91 1230.69,640.19 1253.4,640.19 1265.72,652.5 1288.43,652.5 1350.93,715 U1.5@1542.15,715
NetD3_2: D3.2 R1.2 | length 97.6
  Component Side w15: R1.2@2381.77,1421.18 2381.77,1418.23 2410.9,1389.1 2419.18,1389.1 2448.34,1359.94 D3.2@2448.34,1356
NetD4_2: D4.2 R37.2 | length 90.6
  Component Side w15: v1(1927,1721) 1927.22,1721.22 1953.77,1721.22 D4.2@1969.89,1737.34
  Bottom Layer w15: v1@1928.89,1721 1928.34,1720.45 1928.34,1703.14 1942.37,1689.11 R37.2@1942.37,1686.15
NetD5_A: D5.A D8.K J15.1 J20.1
NetD7_1: D7.1 R27.2 | length 220.1
  Component Side w10: v1(1614,1920) 1737.76,1920 D7.1@1745.76,1928 ; D7.1@1744.93,1928.82 D7.1@1746.06,1929.95
  Bottom Layer w10: R27.2@1535.19,1908.94 1602.94,1908.94 v1(1614,1920)
NetD7_2: D7.2 R28.2 | length 354.9
  Component Side w10: v1(1572.5,1934.5) 1572.5,1931.8 1605.3,1899 1725.54,1899 1745.76,1878.79 D7.2@1745.76,1872.88
  Bottom Layer w10: R28.2@1437.29,1908.94 1437.29,1914.84 1459.1,1936.65 1570.35,1936.65 v1(1572.5,1934.5)
NetD7_3: D7.3 R29.2 | length 526.3
  Component Side w10: v1(1346.94,1873.15) 1350.18,1873.15 1366.03,1889 1493.25,1889 1498.25,1884 1687.03,1884 1727.83,1843.2 1769.22,1843.2 1793,1866.98 D7.3@1793,1872.88
  Bottom Layer w10: R29.2@1339.39,1908.94 1343.87,1904.46 1343.87,1876.22 v1(1346.94,1873.15)
NetD9_2: D9.2 R59.2 | length 191.9
  Component Side w7: D9.2@2461.68,357 D9.2@2462.34,357.66
  Component Side w12: D9.2@2461.68,357 2465,353.68 v1(2465,266)
  Bottom Layer w7: R59.2@2400.85,223.82 2451.77,223.82 2465,237.06 v1(2465,266)
NetD13_1: D13.1 R30.2 | length 355.6
  Bottom Layer w7: R30.2@1822.07,968.31 1822.07,965.35 1796,939.29 1796,859.89 1835.82,820.07 1978.52,820.07 2000.8,842.35 D13.1@2000.8,848.26
NetD13_2: D13.2 R31.2 | length 150.2
  Bottom Layer w7: D13.2@1925.21,848.26 1925.21,884.71 1937.5,897 1937.5,958.79 1943.68,964.97 R31.2@1943.68,990.85
NetJ6_3: J6.3 SB35.1 | length 233.1
  Component Side w7: J6.3@324,798.26 340.19,814.45 419.95,814.45 440.5,835 v1(440.5,862.5)
  Bottom Layer w7: v1(440.5,862.5) 454.53,862.5 494.03,902 SB35.1@494.03,906
NetJ6_4: J6.4 SB34.1 | length 209.8
  Component Side w7: J6.4@324,877 373.21,877 409,912.79 v1@409,913.5
  Bottom Layer w7: v1(406.5,914) 449.53,914 479.31,943.78 485.72,943.78 494.03,952.09 SB34.1@494.03,958
NetJ7_3: J7.3 SB38.1 | length 195.7
  Component Side w7: J7.3@324,1376.74 397.26,1376.74 v1(434,1340)
  Bottom Layer w7: v1(434,1340) 459.28,1314.72 SB38.1@494.03,1314.72
NetJ7_4: J7.4 SB39.1 | length 229.5
  Component Side w7: J7.4@324,1455.48 J7.4@324,1455.48 330.58,1449 v1(421,1449)
  Bottom Layer w7: v1(421,1449) 436.45,1433.55 444.5,1433.55 466,1412.05 466,1383.7 476,1373.7 476,1366.82 480.99,1361.83 SB39.1@494.03,1361.83
NetJ8_3: J8.3 SB36.1 | length 268.7
  Bottom Layer w7: J8.3@324,719.52 429.52,719.52 465,755 465,821.06 494.03,850.09 SB36.1@494.03,856
NetJ8_4: J8.4 SB37.1 | length 260.5
  Bottom Layer w7: J8.4@324,640.78 373.21,640.78 492,759.57 492,799.97 SB37.1@494.03,802
NetJ9_3: J9.3 SB40.1 | length 182.7
  Bottom Layer w7: J9.3@324,1298.22 411.78,1298.22 442.39,1267.61 SB40.1@494.03,1267.61
NetJ9_4: J9.4 SB41.1 | length 700
  Bottom Layer w7: J9.4@324,1219.48 236.52,1219.48 226,1230 226,1495.58 244.92,1514.5 409.72,1514.5 494.03,1430.18 SB41.1@494.03,1408.94
NetL1_1: L1.1 U5.1 U5.2 U5.3
NetQ1_3: Q1.3 R58.1 | length 48.4
  Bottom Layer w15: Q1.3@1513.75,1618 1514.34,1618 1526.62,1630.28 R58.1@1526.62,1660.74
NetQ2_3: Q2.3 R29.1 | length 51.5
  Bottom Layer w10: R29.1@1287.2,1893.28 Q2.3@1310.39,1870.09
  Bottom Layer w12: R29.1@1281.39,1908.94 1287.2,1903.13 R29.1@1287.2,1893.28 ; Q2.3@1310.39,1869.5 Q2.3@1310.39,1870.09
NetQ3_3: Q3.3 R27.1 | length 47.3
  Bottom Layer w10: Q3.3@1458.25,1869.5 1458.25,1870.09 1470.38,1882.21 1470.38,1902.13 R27.1@1477.19,1908.94
NetQ4_3: Q4.3 R28.1 | length 42.5
  Bottom Layer w10: Q4.3@1385.75,1869.5 R28.1@1385.75,1897.34
  Bottom Layer w12: R28.1@1379.29,1908.94 1379.29,1903.15 1385.1,1897.34 R28.1@1385.75,1897.34
NetQ7_3: Q7.3 R15.1 TP3.1 U5.13 | length 447.2
  Bottom Layer w7: TP3.1@1549,1265 1575.5,1238.5 Q7.3@1640.75,1238.5 1643.08,1236.17 1749.37,1236.17 R15.1@1753.74,1231.8 ; R15.1@1753.74,1228.85 R15.1@1753.74,1231.8 ; U5.13@1809.12,1422 1811.14,1422 1813,1420.14 1813,1326.32 1801.4,1314.72 1801.4,1265.4 1783,1247 1768.94,1247 R15.1@1753.74,1231.8
NetR5_1: R5.1 SB46.2 U7.3 | length 174.6
  Bottom Layer w7: R5.1@2006.01,741.52 2006.01,707.93 2010.11,703.83 2035.08,703.83 2052.9,686 2058.81,686 2063.49,686 2071.8,677.69 U7.3@2071.8,615
NetR11_1: R11.1 U3.1 | length 40.2
  Bottom Layer w7: R11.1@1238.26,1102.15 1238.79,1102.68 U3.1@1278.25,1102.68
NetR12_1: R12.1 U3.15 | length 124.9
  Bottom Layer w7: R12.1@1228.26,920.03 1256.03,920.03 1272.5,936.5 1297.5,936.5 1301.92,932.08 1301.92,891.42 U3.15@1303.25,890.08
NetR13_1: R13.1 SB47.2 U7.4 | length 171
  Bottom Layer w7: U7.4@2097.4,615 2097.4,686.64 2110.31,699.55 2115.18,699.55 2123.23,691.5 2159.32,691.5 2166.56,684.26 R13.1@2166.56,672.84 ; R13.1@2168.36,673.36 2169.2,672.51 R13.1@2175.11,672.51
NetR17_1: R17.1 TP20.1 U2.3 | length 196.6
  Bottom Layer w7: U2.3@1618.94,283.2 1609.27,283.2 1609.27,283.45 1601.35,291.37 1566.33,291.37 1550.15,275.2 1550.15,239.63 1563.78,226 1578.31,226 1578.92,225.39 1595.08,225.39 1595.69,226 TP20.1@1626,226
NetR19_2: R19.2 U6.1 | length 72.3
  Bottom Layer w7: R19.2@1514.85,1087.82 1566.63,1087.82 1571,1092.2 U6.1@1571,1106.52
NetR20_2: R20.2 U6.15 | length 86.3
  Bottom Layer w7: R20.2@1592.97,808.85 1595.15,811.03 1595.15,835.45 1596,836.3 U6.15@1596,893.92
NetR22_2: R22.2 U1.6 | length 43.2
  Bottom Layer w7: R22.2@1499.18,752.85 1499.62,752.4 U1.6@1542.15,752.4
NetR26_2: R26.2 TP2.1 U1.3 | length 195.6
  Bottom Layer w7: U1.3@1650.42,677.6 1651.52,676.5 1651.52,672.5 1755.48,672.5 1776.66,693.68 1776.85,693.5 1799.5,693.5 TP2.1@1823,717
NetR33_1: R33.1 R36.2 U5.5 | length 159.7
  Bottom Layer w7: U5.5@1925.26,1481.06 1926.03,1481.83 1944.83,1481.83 1949.37,1486.37 1949.37,1503.19 1955.77,1509.6 1983.38,1509.6 2001.18,1491.8 R36.2@2001.18,1488.85 2001.3,1488.72 2001.3,1437.28 R33.1@2001.43,1437.15
NetSB45_2: SB45.2 U7.1 | length 125.9
  Bottom Layer w10: SB45.2@1948.25,686 1946,683.75 1946,666.22 1981.22,631 2020.6,631 U7.1@2020.6,615
NetTP5_1: TP5.1 U4.2 | length 105.8
  Bottom Layer w7: U4.2@2271,1012.83 2271,993 2280,984 2280,941.69 2300,921.69 TP5.1@2300,919
NetTP8_1: TP8.1 U4.6 | length 78.5
  Bottom Layer w7: TP8.1@2124,1016 2198.71,1016 2200.13,1014.58 U4.6@2200.13,1012.83
NetTP16_1: TP16.1 U3.6 | length 237.8
  Bottom Layer w7: U3.6@1403.25,1102.68 1404.93,1101.01 1404.93,1064.1 1409.03,1060 1465,1060 1479,1074 TP16.1@1479,1191
NetTP17_1: TP17.1 U3.10 | length 284.8
  Bottom Layer w7: TP17.1@1187,961.87 1380.13,961.87 1428.25,913.75 U3.10@1428.25,890.08
NetTP18_1: TP18.1 U6.6 | length 74.6
  Bottom Layer w7: U6.6@1696,1106.52 1696,1158.34 1705.9,1168.24 TP18.1@1705.9,1177
NetTP19_1: TP19.1 U6.10 | length 192.9
  Bottom Layer w7: U6.10@1721,893.92 1721,917.54 1737.37,933.92 1752.78,933.92 1767.6,919.1 1767.6,868 1760,860.4 TP19.1@1760,812.5
PWR_nENABLE: Q7.1 Q8.1 R16.2 R18.2 SB17.2 | length 2835.7
  Component Side w7: v1(1599,1268) 1628,1297 1628,1433 1693,1498 1693,1773 v1(1719,1799)
  Bottom Layer w7: Q8.1@758.6,302.1 758.6,307.9 748.32,318.18 622.84,318.18 568,373.02 568,435.9 577.1,445 577.1,576.13 709,708.03 709,982.58 1103.92,1377.5 1134.47,1377.5 1275.75,1236.22 1476.22,1236.22 1490.5,1250.5 1490.5,1275.32 1508.36,1293.19 1573.81,1293.19 v1(1599,1268) 1600,1269 1624,1269 Q7.1@1625,1270 1625,1296.11 1621.11,1300 1621.11,1321.63 R16.2@1619.58,1323.15 ; v1(1719,1799) 1719,1800.76 1746.92,1828.69 1778.64,1828.69 1793.65,1843.7 1808.51,1843.7 SB17.2@1816.82,1852.01
PWR_PG: R35.1 SB30.1 U5.4 | length 1994.5
  Component Side w7: v1(1750,726) 1750,728.58 1781.96,760.54 1781.96,781.04 1754.9,808.1 1754.9,830.98 1779.64,855.71 1822.26,855.71 1849.5,882.95 1849.5,931 1903.74,985.24 1903.74,1098.24 2049,1243.5 2049,1509 v1(1992,1566)
  Internal Layer 2 w10: v1(1750,726) 1750,697 1836,611 1836,588.66 v1(1837.66,587)
  Bottom Layer w7: v1(1837.66,587) 1837.66,584.85 1835.51,584.85 1821.5,570.84 1821.5,402.35 R35.1@1857.01,366.85 1861.38,362.47 1861.38,329.12 1875,315.5 1927.92,315.5 1934.42,322 1984.05,322 1992.55,313.5 2044.75,313.5 2046.75,315.5 2089,315.5 2091,313.5 2153.5,313.5 2177.37,289.63 SB30.1@2177.37,261 ; U5.4@1896.72,1509.6 1897.49,1510.37 1897.49,1535.49 1928,1566 1991.59,1566 1992,1565.59 v1(1992,1566)
SKY_ADC/RING: J4.9 J19.9 SB13.2 | length 1897.4
  Component Side w7: v1(727.5,1088) 727.5,1086 1102.95,710.55 1134.72,710.55 1148.74,696.54 J19.9@1148.74,668.98 1162.76,654.96 1162.76,508.66 1195.92,475.5 1242.5,475.5 J4.9@1309,409
  Bottom Layer w7: v1(727.5,1088) 893.5,1254 893.5,1556.47 1051.5,1714.47 1051.5,1746.5 1131.75,1826.75 SB13.2@1131.75,1852.19
SKY_CTS: J4.2 J19.2 SB51.1 U6.9 | length 1640.1
  Component Side w7: J19.2@597.56,558.74 597.56,480.44 609,469 J4.2@609,409 J4.2@609,390
  Bottom Layer w7: J4.2@609,409 669.52,469.52 1029.52,469.52 1063,503 1063,616.5 1111,664.5 1275.33,664.5 1338.89,728.06 1469.68,728.06 1482.8,741.18 1482.8,767.19 1491.21,775.6 1708.02,775.6 1717,784.58 1717,809 SB51.1@1718,810 1726.31,818.31 1726.31,850.61 1746,870.3 U6.9@1746,893.92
